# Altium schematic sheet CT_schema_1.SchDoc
size 512 x 488 mm
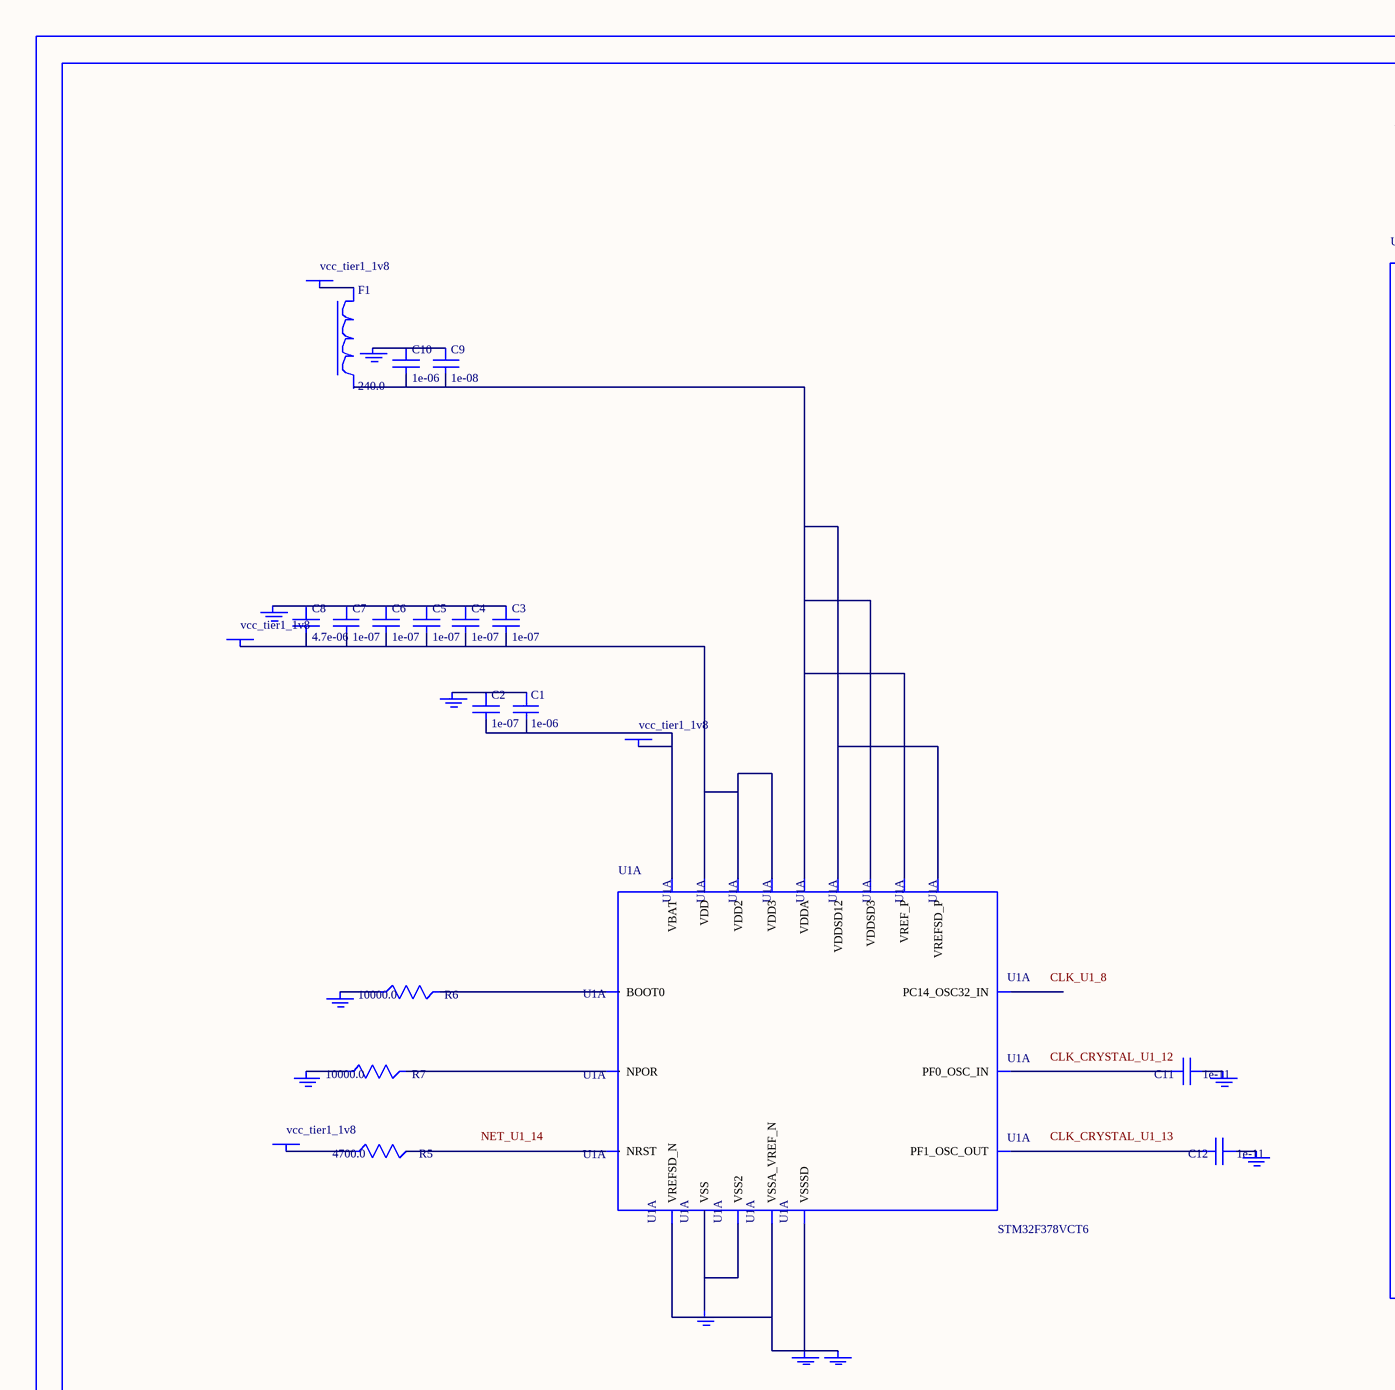
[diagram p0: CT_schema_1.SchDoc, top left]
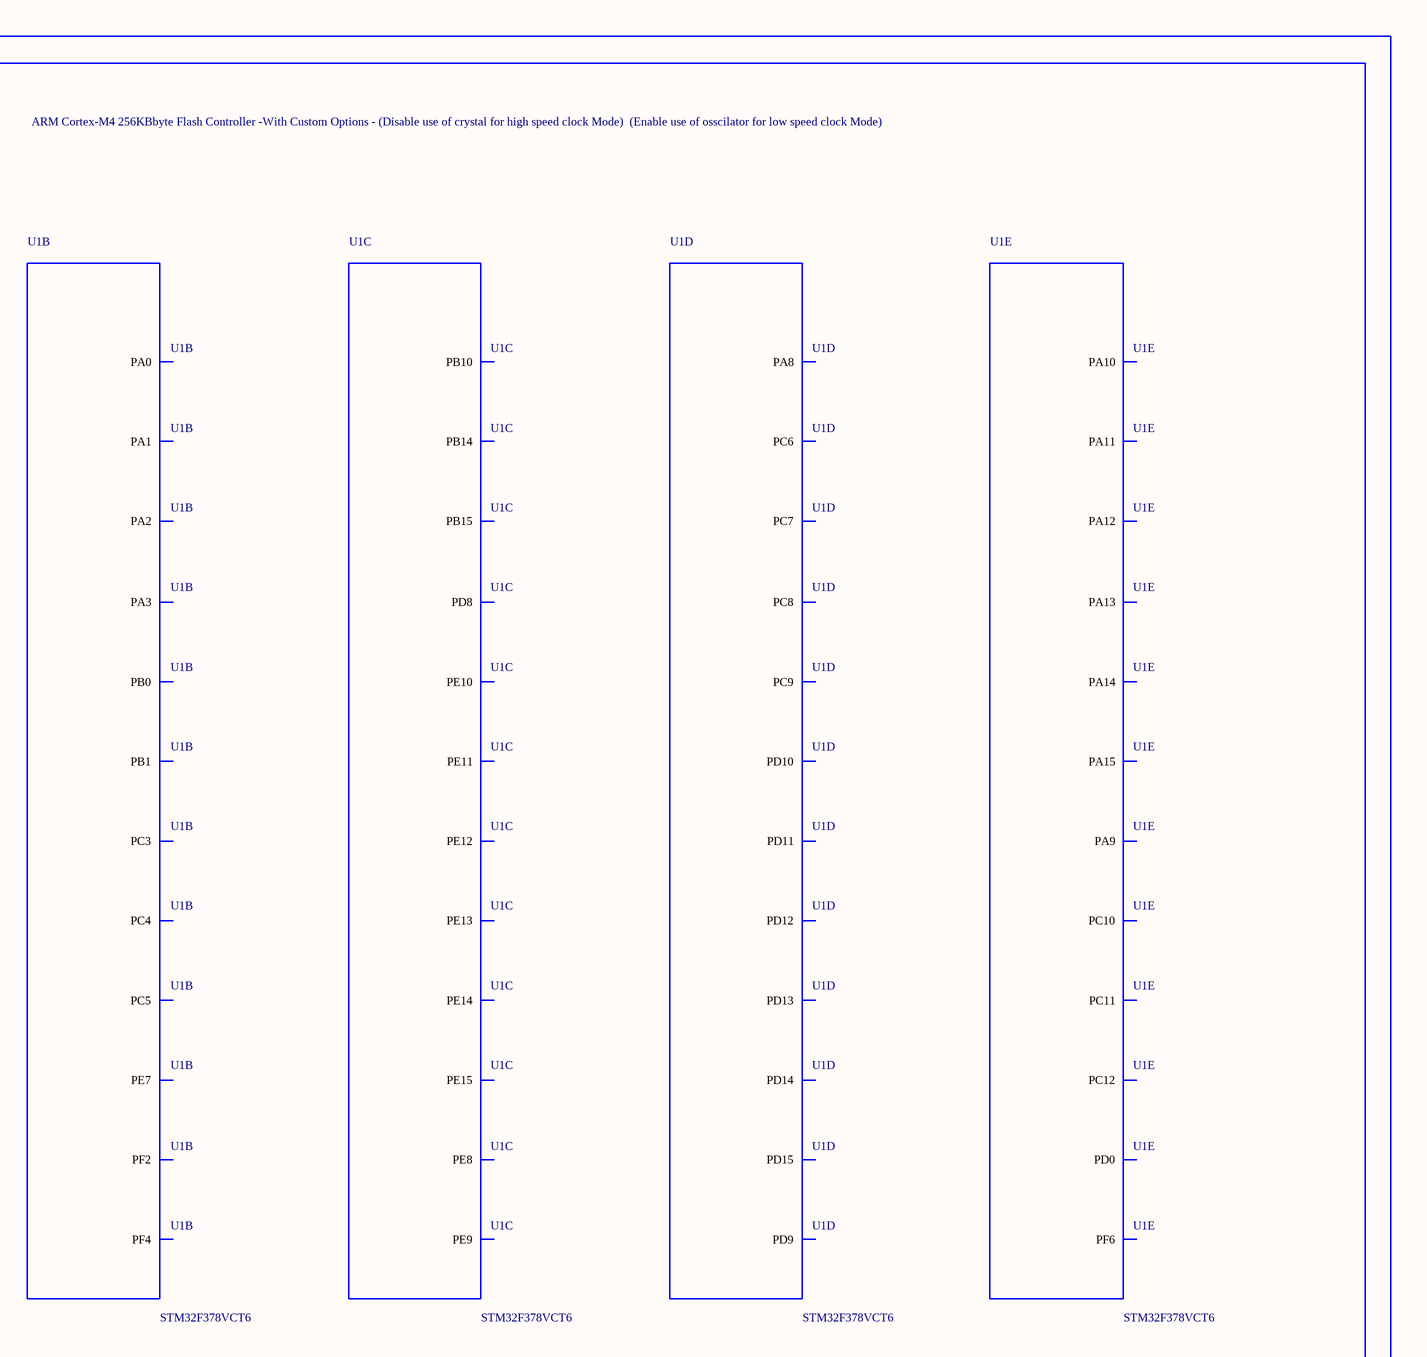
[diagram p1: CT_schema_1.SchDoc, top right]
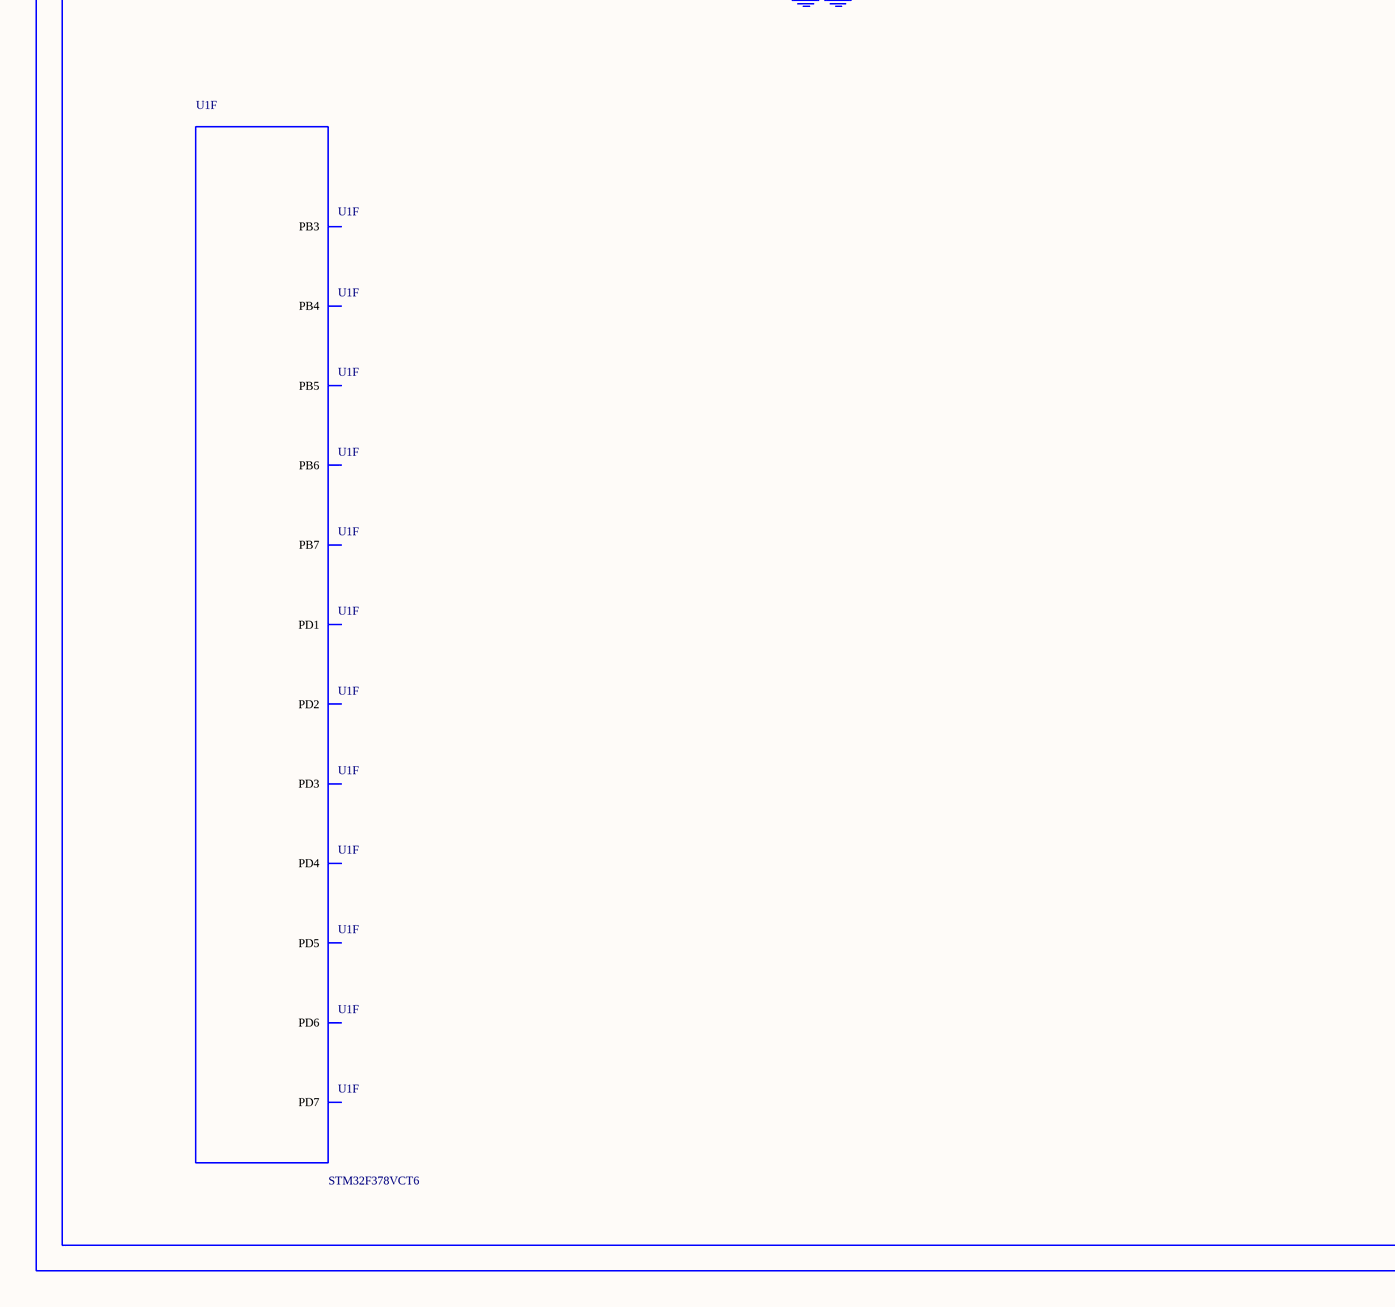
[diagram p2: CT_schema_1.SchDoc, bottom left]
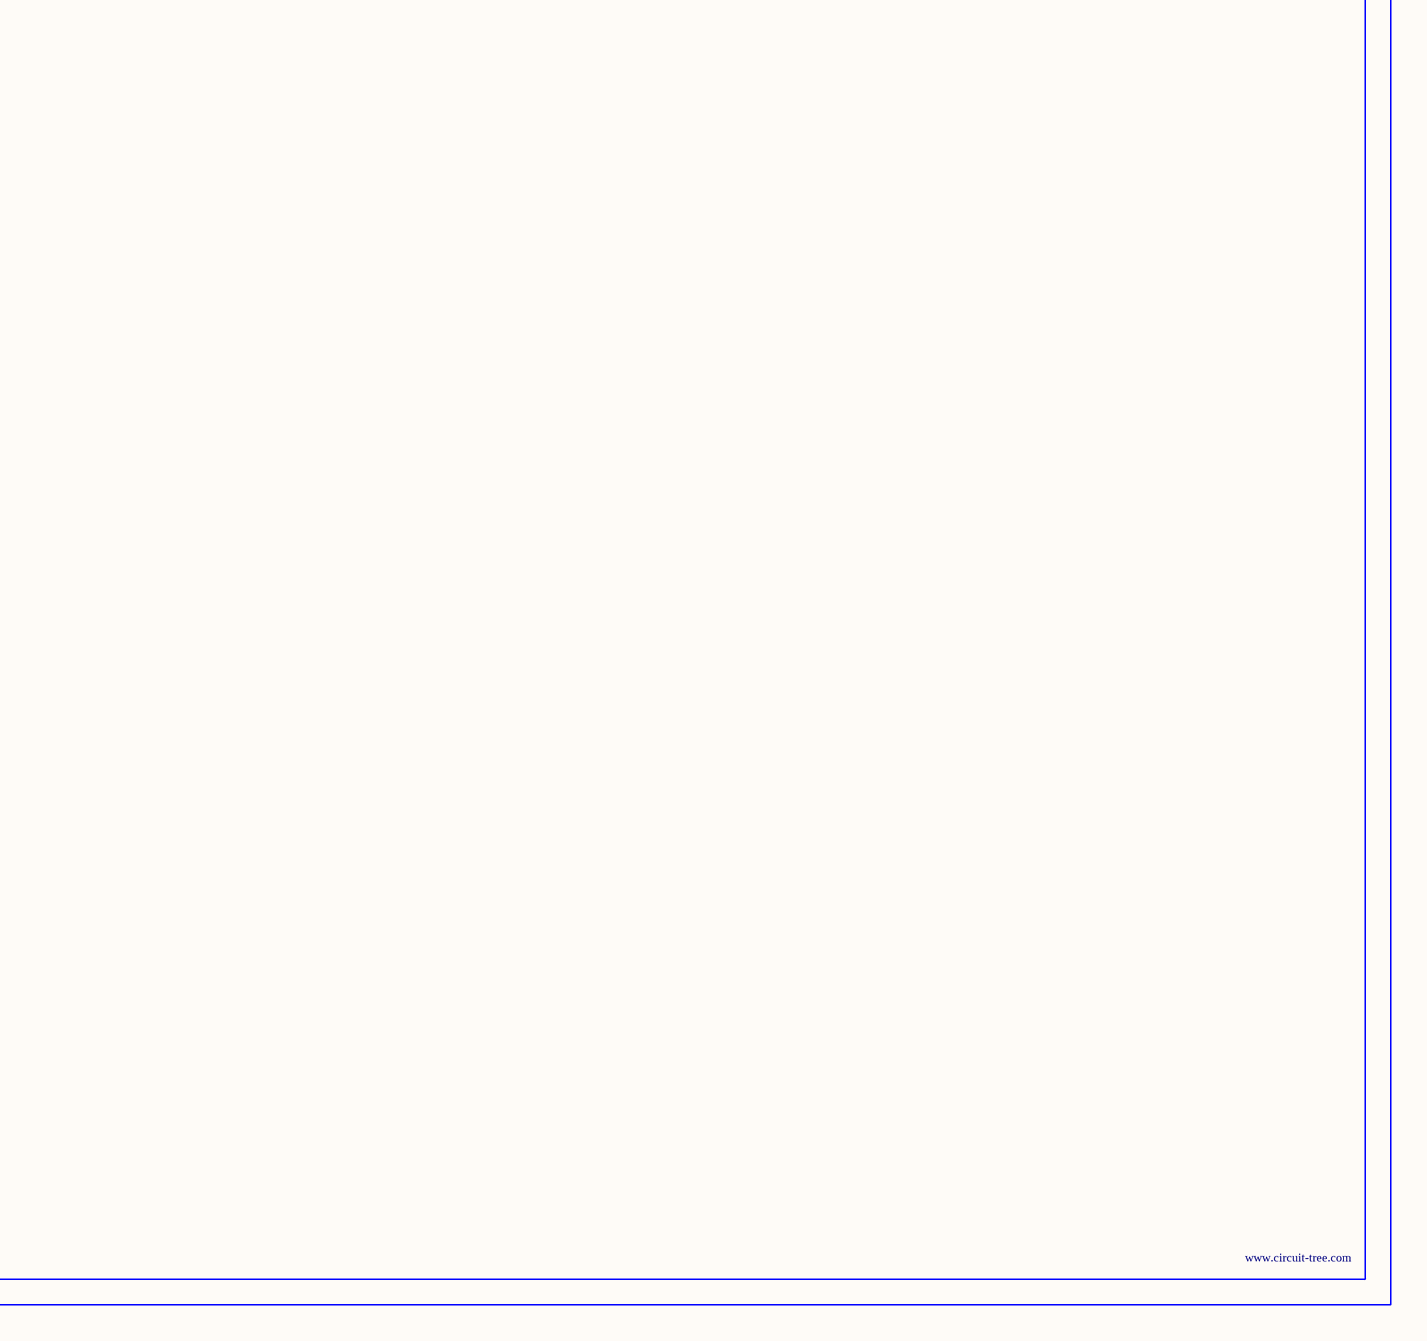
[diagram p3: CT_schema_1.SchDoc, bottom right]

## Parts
BORDER0  (no value)
C1  1e-06  [C0603]
C2  1e-07  [C0603]
C3  1e-07  [C0603]
C4  1e-07  [C0603]
C5  1e-07  [C0603]
C6  1e-07  [C0603]
C7  1e-07  [C0603]
C8  4.7e-06  [C0603]
C9  1e-08  [C0603]
C10  1e-06  [C0603]
C11  1e-11  [C0402]
C12  1e-11  [C0402]
F1  240.0  [L0603]
GND_INSTANCE_0_0  (no value)
GND_INSTANCE_0_1  (no value)
GND_INSTANCE_0_2  (no value)
GND_INSTANCE_0_3  (no value)
GND_INSTANCE_0_4  (no value)
GND_INSTANCE_0_5  (no value)
GND_INSTANCE_0_6  (no value)
GND_INSTANCE_0_7  (no value)
GND_INSTANCE_0_8  (no value)
GND_INSTANCE_0_9  (no value)
POWER_INSTANCE_0_0  vcc_tier1_1v8
POWER_INSTANCE_0_1  vcc_tier1_1v8
POWER_INSTANCE_0_2  vcc_tier1_1v8
POWER_INSTANCE_0_3  vcc_tier1_1v8
R5  4700.0  [R0603]
R6  10000.0  [R0603]
R7  10000.0  [R0603]
U1  STM32F378VCT6  [LQFP100]  (parts A,B,C,D,E,F of 8)

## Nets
NetC1_1: C1.1 C2.1 GND_INSTANCE_0_0.0(GND)
NetC1_2: C1.2 C2.2 POWER_INSTANCE_0_0.0(PWR) U1.6(VBAT)
NetC3_1: C3.1 C4.1 C5.1 C6.1 C7.1 C8.1 GND_INSTANCE_0_5.0(GND)
NetC3_2: C3.2 C4.2 C5.2 C6.2 C7.2 C8.2 POWER_INSTANCE_0_2.0(PWR) U1.28(VDD) U1.75(VDD2) U1.100(VDD3)
NetC9_1: C9.1 C10.1 GND_INSTANCE_0_4.0(GND)
NetC9_2: C9.2 C10.2 U1.21(VDDA) U1.22(VREF_P) U1.50(VDDSD12) U1.51(VDDSD3) U1.52(VREFSD_P)
NetC11_1: C11.1 GND_INSTANCE_0_1.0(GND)
NetC11_2: C11.2 U1.12(PF0_OSC_IN)
NetC12_1: C12.1 GND_INSTANCE_0_2.0(GND)
NetC12_2: C12.2 U1.13(PF1_OSC_OUT)
NetF1_1: F1.1 POWER_INSTANCE_0_1.0(PWR)
NetGND_INSTANCE_0_3_0: GND_INSTANCE_0_3.0(GND) GND_INSTANCE_0_7.0(GND) U1.20(VSSA_VREF_N) U1.48(VREFSD_N) U1.49(VSSSD)
NetGND_INSTANCE_0_6_0: GND_INSTANCE_0_6.0(GND) R7.1
NetGND_INSTANCE_0_8_0: GND_INSTANCE_0_8.0(GND) R6.1
NetGND_INSTANCE_0_9_0: GND_INSTANCE_0_9.0(GND) U1.74(VSS) U1.99(VSS2)
NetPOWER_INSTANCE_0_3_0: POWER_INSTANCE_0_3.0(PWR) R5.1
NetR5_2: R5.2 U1.14(NRST)
NetR6_2: R6.2 U1.94(BOOT0)
NetR7_2: R7.2 U1.37(NPOR)

Not connected (* = marked no-connect by the designer): F1 2; U1 8(PC14_OSC32_IN) 18(PC3) 19(PF2) 23(PA0) 24(PA1) 25(PA2) 26(PA3) 27(PF4) 33(PC4) 34(PC5) 35(PB0) 36(PB1) 38(PE7) 39(PE8) 40(PE9) 41(PE10) 42(PE11) 43(PE12) 44(PE13) 45(PE14) 46(PE15) 47(PB10) 53(PB14) 54(PB15) 55(PD8) 56(PD9) 57(PD10) 58(PD11) 59(PD12) 60(PD13) 61(PD14) 62(PD15) 63(PC6) 64(PC7) 65(PC8) 66(PC9) 67(PA8) 68(PA9) 69(PA10) 70(PA11) 71(PA12) 72(PA13) 73(PF6) 76(PA14) 77(PA15) 78(PC10) 79(PC11) 80(PC12) 81(PD0) 82(PD1) 83(PD2) 84(PD3) 85(PD4) 86(PD5) 87(PD6) 88(PD7) 89(PB3) 90(PB4) 91(PB5) 92(PB6) 93(PB7)

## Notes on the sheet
- Labels drawn without touching a wire or pin: CLK_CRYSTAL_U1_12, CLK_CRYSTAL_U1_13, CLK_U1_8, NET_U1_14

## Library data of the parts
BORDER0 = BORDER_PAGE0
C1 C10 = C0603C105K3RACTU
C2-C7 = 06035C104K4Z2A
C8 = GRM188R6YA475KE15D
C9 = 06035C103K4Z2A
C11 C12 = C0402C100K3GACTU
F1 = Z0603C241ASMST
GND_INSTANCE_0_0-GND_INSTANCE_0_9 = GND
POWER_INSTANCE_0_0-POWER_INSTANCE_0_3 = PWR
R5 = RC0603JR-074K7L
R6 R7 = RC0603JR-0710KL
